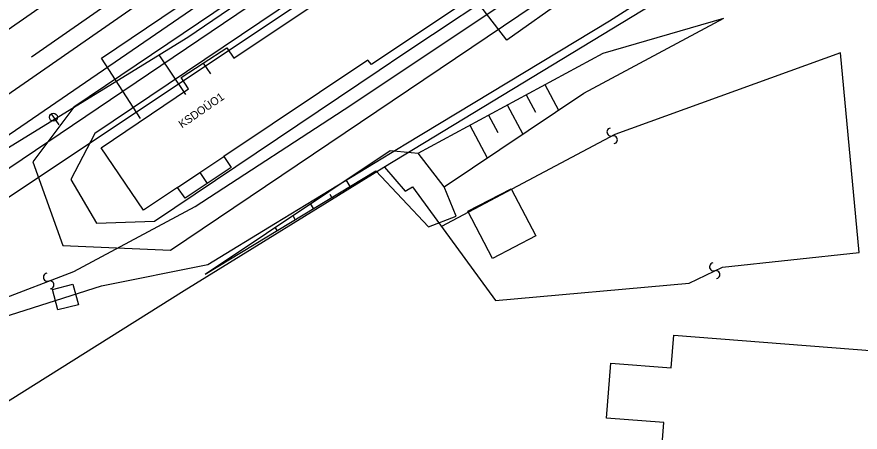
# Model space of a CAD drawing. Extents: x -469926 to -462499, y -1098642 to -1092733.
# Drawn here: x -469856 to -469777, y -1098567 to -1098528.2 of the extents above; entities that cross this region are included whole.
import ezdxf

# ---------------------------------------------------------------- set-up
doc = ezdxf.new("R2010")
doc.units = 0
for name, color, linetype in [('Vrstva 1', 7, 'Continuous'), ('Vrstva 10', 7, 'Continuous'), ('Vrstva 12', 7, 'Continuous'), ('Vrstva 13', 7, 'Continuous'), ('Vrstva 16', 7, 'Continuous'), ('Vrstva 26', 7, 'Continuous'), ('Vrstva 3', 7, 'Continuous'), ('Vrstva 40', 7, 'Continuous'), ('Vrstva 44', 7, 'Continuous'), ('Vrstva 46', 7, 'Continuous'), ('Vrstva 48', 7, 'Continuous'), ('Vrstva 50', 7, 'Continuous'), ('Vrstva 51', 7, 'Continuous'), ('Vrstva 52', 7, 'Continuous'), ('Vrstva 6', 7, 'Continuous'), ('Vrstva 62', 7, 'Continuous')]:
    doc.layers.add(name, color=color, linetype=linetype)

msp = doc.modelspace()

# ---------------------------------------------------------------- linework, layer by layer
at = {"layer": 'Vrstva 1'}
for p, q in [((-469824.757, -1098536.462), (-469799.038, -1098519.273)), ((-469778.887, -1098531.553), (-469800.02, -1098539.19)), ((-469777.115, -1098550.236), (-469778.887, -1098531.553)), ((-469839.346, -1098545.938), (-469824.757, -1098536.462)), ((-469800.02, -1098539.19), (-469816.268, -1098547.799)), ((-469821.606, -1098542.253), (-469819.652, -1098544.509)), ((-469819.652, -1098544.509), (-469818.971, -1098544.099)), ((-469818.971, -1098544.099), (-469811.199, -1098554.737)), ((-469850.714, -1098552.003), (-469839.346, -1098545.938)), ((-469789.931, -1098551.6), (-469777.115, -1098550.236)), ((-469793.067, -1098553.1), (-469789.931, -1098551.6)), ((-469863.03, -1098556.741), (-469850.714, -1098552.003)), ((-469811.199, -1098554.737), (-469793.067, -1098553.1))]:
    msp.add_line(p, q, dxfattribs=at)
at = {"layer": 'Vrstva 10'}
msp.add_lwpolyline([(-469674.733, -1098418.222), (-469677.463, -1098420.356), (-469677.12, -1098420.87), (-469693.38, -1098433.29), (-469665.98, -1098471.6), (-469664.75, -1098473.16), (-469677.56, -1098480.77), (-469693.89, -1098490.89), (-469741.7, -1098494.01), (-469774.48, -1098513.68), (-469784.5, -1098519.73), (-469821.65, -1098542.28), (-469840.35, -1098553.83), (-469861.33, -1098566.96), (-469892.02, -1098573.54), (-469900, -1098575.209)], dxfattribs=at)
at = {"layer": 'Vrstva 12'}
for points in [[(-469813.791, -1098546.382), (-469809.731, -1098544.264), (-469807.429, -1098548.676), (-469811.488, -1098550.794)], [(-469800.396, -1098560.599), (-469794.725, -1098561.041), (-469794.485, -1098557.973), (-469729.291, -1098563.056), (-469730.118, -1098573.67), (-469795.624, -1098568.563), (-469795.437, -1098566.151), (-469800.796, -1098565.733)]]:
    msp.add_lwpolyline(points, close=True, dxfattribs=at)
at = {"layer": 'Vrstva 13'}
for points in [[(-469713.863, -1098486.175), (-469719.735, -1098482.419), (-469734.102, -1098478.591), (-469744.403, -1098478.575), (-469755.474, -1098482.087), (-469793.629, -1098508.612), (-469796.143, -1098509.959), (-469798.81, -1098510.547), (-469806.978, -1098510.316), (-469809.468, -1098510.203), (-469812.7, -1098511.036), (-469850.715, -1098536.632), (-469854.532, -1098541.741), (-469851.736, -1098549.591), (-469841.642, -1098550.002), (-469804.517, -1098525.008), (-469795.462, -1098518.113), (-469788.948, -1098512.578)], [(-469810.937, -1098513.674), (-469848.739, -1098539.1), (-469850.995, -1098543.413), (-469848.577, -1098547.493)], [(-469848.577, -1098547.493), (-469843.134, -1098547.303), (-469822.086, -1098533.166), (-469819.865, -1098531.686), (-469808.852, -1098524.346), (-469806.376, -1098522.59)]]:
    msp.add_lwpolyline(points, dxfattribs=at)
at = {"layer": 'Vrstva 16'}
msp.add_line((-469852.834, -1098537.27), (-469852.104, -1098538.286), dxfattribs=at)
msp.add_circle((-469852.615, -1098537.575), 0.375, dxfattribs=at)
at = {"layer": 'Vrstva 26'}
msp.add_lwpolyline([(-469897.326, -1098569.025), (-469848.102, -1098553.339), (-469838.138, -1098551.354), (-469831.797, -1098547.48), (-469819.583, -1098540.072), (-469800.507, -1098528.557), (-469781.435, -1098516.382), (-469748.537, -1098496.249), (-469742.187, -1098492.526), (-469729.539, -1098492.137), (-469717.963, -1098472.762), (-469719.534, -1098467.181), (-469717.122, -1098466.341), (-469714.881, -1098471.546), (-469710.445, -1098470.45)], dxfattribs=at)
at = {"layer": 'Vrstva 40'}
for p, q in [((-469840.027, -1098530.086), (-469804.991, -1098506.28)), ((-469856.98, -1098540.495), (-469840.027, -1098530.086)), ((-469842.726, -1098531.743), (-469840.233, -1098535.445))]:
    msp.add_line(p, q, dxfattribs=at)
at = {"layer": 'Vrstva 44'}
msp.add_line((-469888.221, -1098563.538), (-469828.397, -1098523.171), dxfattribs=at)
at = {"layer": 'Vrstva 46'}
for p, q in [((-469848.113, -1098532.045), (-469811.572, -1098507.406)), ((-469844.446, -1098537.683), (-469848.113, -1098532.045))]:
    msp.add_line(p, q, dxfattribs=at)
at = {"layer": 'Vrstva 48'}
for p, q in [((-469806.572, -1098534.528), (-469805.282, -1098536.923)), ((-469808.333, -1098535.477), (-469807.45, -1098537.115)), ((-469810.093, -1098536.425), (-469808.622, -1098539.155)), ((-469811.854, -1098537.374), (-469810.971, -1098539.012)), ((-469813.615, -1098538.323), (-469811.963, -1098541.388))]:
    msp.add_line(p, q, dxfattribs=at)
at = {"layer": 'Vrstva 50'}
for p, q in [((-469787.08, -1098514.09), (-469810.146, -1098530.364)), ((-469810.146, -1098530.364), (-469813.461, -1098526.027))]:
    msp.add_line(p, q, dxfattribs=at)
at = {"layer": 'Vrstva 51'}
for p, q in [((-469888.777, -1098566.318), (-469827.862, -1098525.78)), ((-469892.096, -1098563.38), (-469839.186, -1098527.15))]:
    msp.add_line(p, q, dxfattribs=at)
for centre, radius, start, end in [((-469800.381, -1098538.962), 0.377, 100.00432, 287.66753), ((-469800.156, -1098539.68), 0.376, 280.68036, 106.99149), ((-469790.771, -1098551.588), 0.377, 100.00432, 287.66753), ((-469853.168, -1098552.544), 0.377, 100.00432, 287.66753), ((-469790.547, -1098552.307), 0.376, 280.68036, 106.99149), ((-469852.944, -1098553.263), 0.376, 280.68036, 106.99149)]:
    msp.add_arc(centre, radius, start, end, dxfattribs=at)
at = {"layer": 'Vrstva 52'}
msp.add_line((-469854.678, -1098531.913), (-469816.847, -1098505.713), dxfattribs=at)
at = {"layer": 'Vrstva 6'}
for p, q in [((-469838.577, -1098532.508), (-469837.892, -1098533.529)), ((-469838.904, -1098542.755), (-469838.211, -1098543.793))]:
    msp.add_line(p, q, dxfattribs=at)
for points in [[(-469904.106, -1098562.074), (-469881.523, -1098546.432), (-469857.681, -1098529.918), (-469817.932, -1098502.342), (-469796.028, -1098487.179), (-469777.322, -1098474.241), (-469770.533, -1098469.535)], [(-469901.402, -1098566.189), (-469878.709, -1098550.52), (-469854.94, -1098534.108), (-469815.116, -1098506.486), (-469793.261, -1098491.355), (-469774.463, -1098478.318), (-469767.613, -1098473.573)], [(-469818.856, -1098519.946), (-469814.032, -1098516.722), (-469811.489, -1098515.032), (-469806.795, -1098521.93), (-469809.333, -1098523.627), (-469820.335, -1098530.984), (-469822.828, -1098532.651), (-469823.146, -1098532.225), (-469836.649, -1098541.248), (-469835.965, -1098542.272), (-469838.211, -1098543.793), (-469840.276, -1098545.142), (-469840.996, -1098544.153), (-469844.165, -1098546.287), (-469848.131, -1098540.451), (-469839.944, -1098534.907), (-469840.636, -1098533.872), (-469838.577, -1098532.508), (-469836.353, -1098531.081), (-469835.698, -1098532.056), (-469827.154, -1098526.318)], [(-469840.996, -1098544.153), (-469838.904, -1098542.755), (-469836.649, -1098541.248)]]:
    msp.add_lwpolyline(points, dxfattribs=at)
at = {"layer": 'Vrstva 62'}
for p, q in [((-469824.816, -1098544.054), (-469825.189, -1098543.435)), ((-469826.529, -1098545.087), (-469826.696, -1098544.809)), ((-469828.241, -1098546.12), (-469828.52, -1098545.657)), ((-469829.954, -1098547.153), (-469830.121, -1098546.875)), ((-469831.666, -1098548.186), (-469831.851, -1098547.879))]:
    msp.add_line(p, q, dxfattribs=at)
for points in [[(-469838.411, -1098552.254), (-469821.077, -1098540.693), (-469818.447, -1098540.928), (-469801.094, -1098531.575), (-469789.811, -1098528.303)], [(-469816.02, -1098544.099), (-469802.905, -1098535.334), (-469789.811, -1098528.303)], [(-469838.411, -1098552.254), (-469822.404, -1098542.599), (-469817.461, -1098547.83), (-469814.887, -1098546.833), (-469816.02, -1098544.099), (-469818.447, -1098540.928)], [(-469852.7, -1098553.712), (-469850.803, -1098553.197), (-469850.259, -1098555.139), (-469852.193, -1098555.588), (-469852.7, -1098553.712)]]:
    msp.add_lwpolyline(points, dxfattribs=at)

# ---------------------------------------------------------------- texts
at = {"layer": 'Vrstva 3'}
msp.add_text('KSDOÚO1', height=0.75, rotation=34.69276, dxfattribs=at).set_placement((-469840.566, -1098538.633))

doc.saveas('drawing.dxf')
